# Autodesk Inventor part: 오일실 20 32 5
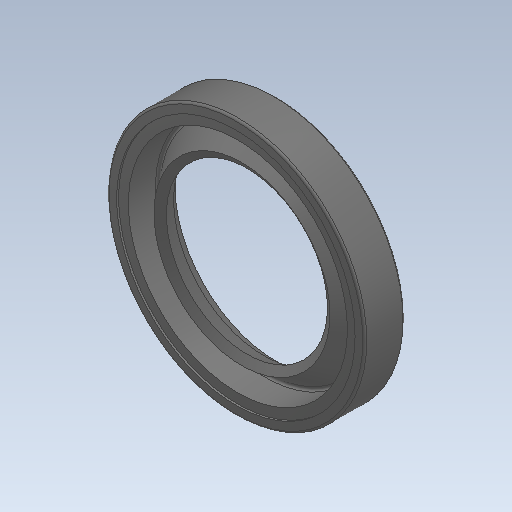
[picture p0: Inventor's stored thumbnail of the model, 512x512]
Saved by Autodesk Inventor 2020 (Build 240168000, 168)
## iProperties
Created: 2024-08
Part Number: 오일실 20 32 5
Material: 고무
Description: 오일 실 - 비스프링, 조립 GA
Document SubType Name: Modeling
Designer: oem
Density: 0.93 g/cm^3
Appearance: 기본값
Author: jhkim
Sending System: Autodesk Inventor 2025
Preprocessor: ST-DEVELOPER v20
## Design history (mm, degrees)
node "오일실 20 32 51"
node "솔리드1"
body "Solid1"
